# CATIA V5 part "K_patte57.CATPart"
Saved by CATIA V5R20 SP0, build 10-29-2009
Part number: patte 57
Publications: "demi largeur balancier", "epaisseur pieces", "Plan.-30", "liaison 57/23", "liaison 57/50"
Bounding box of the stored display mesh (mm): x -30 to 0, y -744.994 to -640.005, z 700.005 to 814.998
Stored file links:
  G:\Khaled_CFAO_2011\SIL\SIL_GR2\mdardier\Khaled\CAD_ThinkMOTION\K_patte57.CATPart
  G:\Khaled_CFAO_2011\SIL\SIL_GR2\mdardier\Khaled\CAD_ThinkMOTION\K_ass_tandem.CATProduct
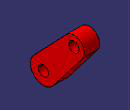
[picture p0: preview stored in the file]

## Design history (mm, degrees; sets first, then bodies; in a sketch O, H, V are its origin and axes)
External parameters (linked from other documents)
  `External.demi largeur balancier` = 50 mm
  `External.epaisseur pieces` = 30 mm
Set1
  Plane1 "Plan.-30": linked copy from another document
  Point1 "liaison 57/23": linked copy from another document
  Point2 "liaison 57/50": linked copy from another document
Body1 (main body)
  Sketch1 on Plane1, origin (-30, 0, 0), H (0, 1, 0), V (0, 0, 1)
    circle A1 centre (-720, 725) radius 10
    point P1 (-720, 725)
    reference projected point E1 (-720, 725) from Point1
    arc A2 centre (-720, 725) radius 25 from (-738.0711, 742.2753) to (-700.1642, 709.7836) ccw
    point P2 (-720, 725)
    reference projected point E2 (-720, 725) from Point1
    circle A3 centre (-660, 795) radius 10
    point P3 (-660, 795)
    reference projected point E3 (-660, 795) from Point2
    arc A4 centre (-660, 795) radius 20 from (-644.1313, 782.8269) to (-674.4569, 808.8202) ccw
    point P4 (-660, 795)
    reference projected point E4 (-660, 795) from Point2
    line L1 (-738.0711, 742.2753) -> (-674.4569, 808.8202)
    line L2 (-700.1642, 709.7836) -> (-644.1313, 782.8269)
    radius A1 = 10 {= `External.demi largeur balancier` /5}
    radius A2 = 25 {= `External.demi largeur balancier` /2}
    radius A3 = 10 {= `External.demi largeur balancier` /5}
    radius A4 = 20 {= `External.demi largeur balancier` *2/5}
    coincidence: P1 E1, P2 E2, P3 E3, P4 E4
    tangency: L1 A4, L2 A4, L1 A2, L2 A2
  Pad1: profile Sketch1, direction (1, 0, 0), length 30 {= `External.epaisseur pieces`}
